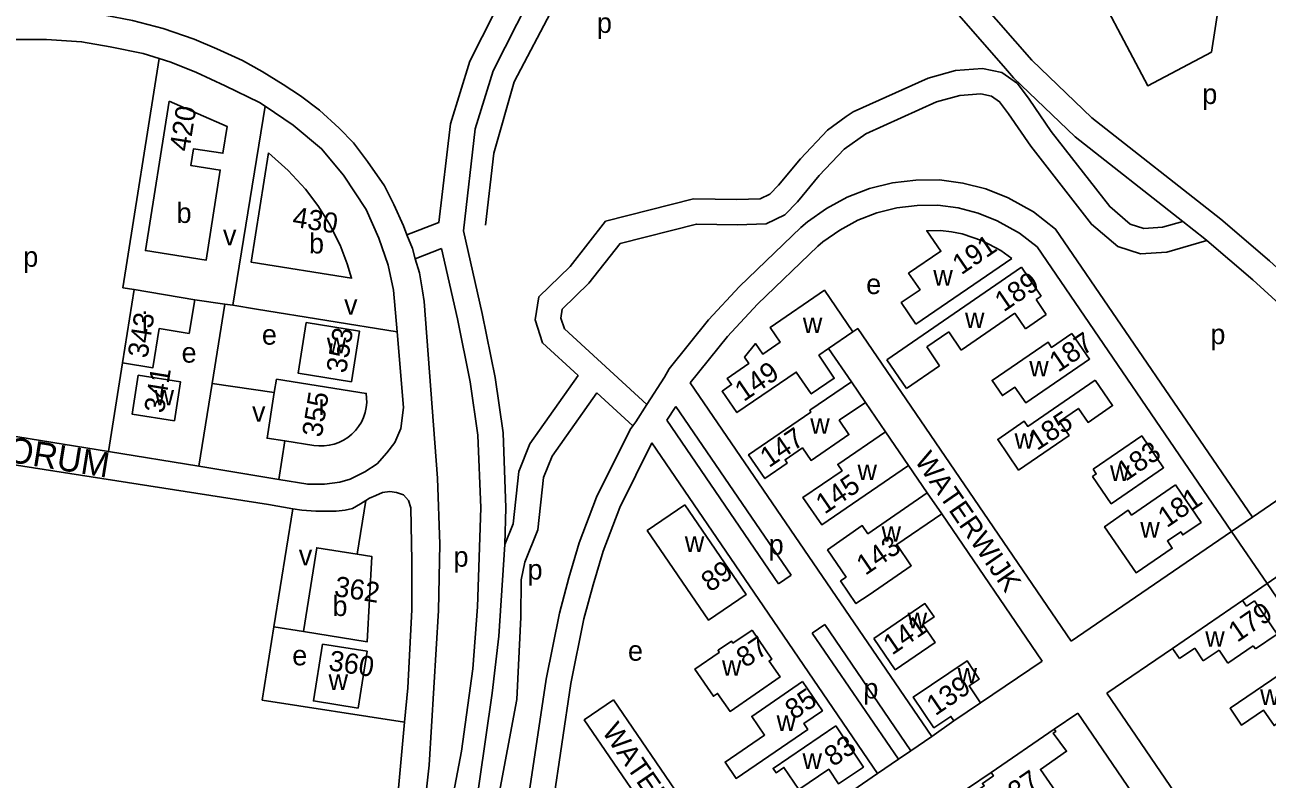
# Model space of a CAD drawing. Extents: x 154320 to 156262, y 382651 to 384180.
# Drawn here: x 155307.4 to 155553.7, y 383322.8 to 383472.2 of the extents above; entities that cross this region are included whole.
import ezdxf

# ---------------------------------------------------------------- set-up
doc = ezdxf.new("R2010")
doc.units = 0
for name, color, linetype in [('BLT_Basislijn', 7, 'Continuous'), ('BLT_Bebouwing', 7, 'Continuous'), ('BLT_Centroide', 7, 'Continuous'), ('BLT_Huisnummer', 7, 'Continuous'), ('BLT_Straatnaam', 7, 'Continuous'), ('BLT_Vlakafsluiter', 7, 'Continuous')]:
    doc.layers.add(name, color=color, linetype=linetype)

msp = doc.modelspace()

# ---------------------------------------------------------------- linework, layer by layer
at = {"layer": 'BLT_Basislijn'}
for p, q in [((155347.08, 383416.87), (155341.13, 383417.73)), ((155347.08, 383416.87), (155344.56, 383401.15)), ((155348.64, 383416.64), (155347.08, 383416.87)), ((155471.24, 383401.47), (155466.74, 383408.06)), ((155326.75, 383405.24), (155323.99, 383387.63)), ((155344.56, 383401.15), (155341.92, 383384.73)), ((155439.3, 383401.25), (155487.17, 383331.21)), ((155436.42, 383396.6), (155459.29, 383363.15)), ((155477.99, 383391.56), (155474.03, 383397.39)), ((155456.81, 383361.45), (155434.66, 383393.86)), ((155358.95, 383389.76), (155357.73, 383382.13)), ((155452.89, 383358.32), (155431.66, 383389.39)), ((155373.27, 383367.31), (155374.97, 383377.96)), ((155546.61, 383371.83), (155514.83, 383350.11)), ((155553.66, 383361.51), (155557.79, 383364.33)), ((155456.81, 383361.45), (155459.29, 383363.15)), ((155548.79, 383358.16), (155553.66, 383361.51)), ((155476.44, 383323.87), (155452.89, 383358.32)), ((155362.62, 383352), (155356.79, 383352.93)), ((155463.49, 383351.67), (155465.97, 383353.37)), ((155480.57, 383326.69), (155463.49, 383351.67)), ((155465.97, 383353.37), (155483.05, 383328.38)), ((155521.89, 383339.79), (155534.9, 383348.67)), ((155509.05, 383346.16), (155496.84, 383337.85)), ((155521.89, 383339.79), (155585.65, 383246.5)), ((155491.56, 383334.34), (155487.17, 383331.21)), ((155511.44, 383332.68), (155516.11, 383335.84)), ((155516.11, 383335.84), (155555.91, 383277.62)), ((155487.17, 383331.21), (155483.05, 383328.38)), ((155483.05, 383328.38), (155480.57, 383326.69)), ((155480.57, 383326.69), (155476.44, 383323.87)), ((155476.44, 383323.87), (155447.55, 383304.12)), ((155494.24, 383320.89), (155498.93, 383324.09))]:
    msp.add_line(p, q, dxfattribs=at)
for points in [[(155698.05, 383531.88), (155690.89, 383537.69), (155681.93, 383540.29), (155671.11, 383539.57), (155664.57, 383538.95), (155596.99, 383507.93), (155581.65, 383515.6), (155558.93, 383498.71), (155544.8, 383480.89), (155542.65, 383466.76)], [(155473.87, 383522.91), (155483.98, 383497.86), (155486.36, 383493.38), (155496.62, 383477.01), (155506.99, 383465.16), (155518.91, 383453.74), (155544.48, 383433.68), (155554.14, 383425.4), (155573.89, 383407.44), (155578.88, 383402.26), (155583.05, 383396.74)], [(155469.2, 383521.12), (155479.44, 383495.74), (155482.03, 383490.88), (155492.59, 383474.01), (155501.8, 383463.51)], [(155465.31, 383513.49), (155448.18, 383506.86), (155432.53, 383497.96), (155422.89, 383489.79), (155412.29, 383475.83), (155404.43, 383460.88), (155400.38, 383446.77), (155398.74, 383432.48)], [(155542.65, 383466.76), (155530.01, 383460.09), (155516.89, 383484.95), (155499.97, 383479.97), (155484.43, 383512.94)], [(155421.03, 383501.28), (155409.88, 383490.01), (155402.96, 383479.51), (155395.61, 383464.95), (155391.76, 383452.59), (155389.49, 383433.02), (155383.15, 383430.57)], [(155424.44, 383497.62), (155413.79, 383486.85), (155407.29, 383476.99), (155400.26, 383463.07), (155396.67, 383451.55), (155394.33, 383431.37)], [(155296.71, 383474.89), (155302.03, 383475.13), (155307.58, 383475.24), (155313.6, 383475.13), (155318.8, 383474.65), (155323.28, 383474.06), (155328.72, 383473), (155334.86, 383471.46), (155341, 383469.34), (155345.49, 383467.45), (155350.56, 383465.08), (155354.46, 383462.96), (155358.59, 383460.36), (155362.02, 383458.11), (155365.8, 383455.28), (155369.69, 383451.73), (155372.53, 383448.78), (155375.36, 383445.12), (155378.67, 383440.28), (155380.56, 383436.61), (155382.45, 383432.36), (155383.15, 383430.57)], [(155304.29, 383469.27), (155311.69, 383469.27), (155318.65, 383468.83), (155324.31, 383467.82), (155330.84, 383466.51), (155334.05, 383465.5)], [(155329.08, 383419.74), (155326.85, 383420.09), (155334.05, 383465.5)], [(155334.05, 383465.5), (155336.36, 383464.77), (155341.43, 383462.74), (155347.09, 383460.12), (155353.91, 383456.78), (155355.02, 383456.04)], [(155501.05, 383462.74), (155497.22, 383463.53), (155491.9, 383463.14), (155486.45, 383461.64), (155471.59, 383454.96), (155470.24, 383454)], [(155536.92, 383433.25), (155532.93, 383432.09), (155529.19, 383431.84), (155526.54, 383432.7), (155522.47, 383436.16), (155510.84, 383451.07), (155506.47, 383457.45), (155504.15, 383460.56), (155501.05, 383462.74)], [(155501.8, 383463.51), (155503.38, 383461.7), (155515.63, 383449.96), (155536.92, 383433.25)], [(155541.74, 383429.44), (155533.8, 383427.14), (155528.56, 383426.79), (155524.06, 383428.25), (155518.84, 383432.68), (155506.8, 383448.12), (155502.4, 383454.54), (155500.62, 383456.93), (155499.02, 383458.05), (155496.88, 383458.5), (155492.75, 383458.19), (155488.15, 383456.92), (155474.09, 383450.6), (155469.81, 383447.56), (155464.88, 383442.33), (155460.54, 383437.08), (155458.05, 383434.51), (155454.34, 383432.77), (155448.58, 383432.55), (155440.53, 383432.69), (155425.41, 383428.83), (155419.22, 383420.97), (155413.95, 383415.85), (155413.67, 383414.1), (155414.35, 383411.97), (155430.71, 383396.96)], [(155355.02, 383456.04), (155348.64, 383416.64)], [(155355.02, 383456.04), (155360.59, 383452.29), (155366.24, 383447.64), (155370.6, 383442.42), (155375.09, 383435.59), (155377.56, 383429.93), (155379.45, 383424.56), (155380.46, 383419.63), (155381.19, 383411.37)], [(155470.24, 383454), (155466.51, 383451.34), (155461.13, 383445.64), (155456.81, 383440.42), (155455.1, 383438.64), (155453.14, 383437.73), (155448.52, 383437.55), (155439.95, 383437.7), (155422.53, 383433.26)], [(155550.74, 383374.65), (155511.74, 383431.71), (155507.33, 383435.11), (155502.31, 383437.9), (155497.93, 383439.67), (155493.37, 383440.82), (155488.7, 383441.44), (155484, 383441.4), (155479.37, 383440.85), (155474.82, 383439.73), (155470.4, 383438.04), (155466.3, 383435.78), (155462.55, 383433.16), (155461.26, 383432.06), (155449.1, 383420.32), (155442.92, 383413.75), (155435.14, 383404.06), (155434.19, 383402.37), (155430.71, 383396.96)], [(155546.61, 383371.83), (155508.06, 383428.23), (155504.57, 383430.92), (155500.15, 383433.38), (155496.37, 383434.9), (155492.43, 383435.9), (155488.39, 383436.43), (155484.32, 383436.41), (155480.27, 383435.92), (155476.32, 383434.95), (155472.51, 383433.5), (155468.95, 383431.53), (155465.61, 383429.2), (155464.62, 383428.36), (155452.66, 383416.81), (155446.69, 383410.46), (155439.3, 383401.25)], [(155422.53, 383433.26), (155415.5, 383424.32), (155409.27, 383418.28), (155408.54, 383413.71), (155410, 383409.18), (155417.06, 383402.7)], [(155536.92, 383433.25), (155541.31, 383429.81), (155541.74, 383429.44)], [(155383.15, 383430.57), (155384.22, 383427.87), (155384.81, 383425.85)], [(155394.33, 383431.37), (155398.09, 383414.99), (155400.64, 383402.31), (155402.2, 383391.37), (155402.77, 383376.53), (155402.53, 383369.27)], [(155390.01, 383427.86), (155384.81, 383425.85)], [(155390.01, 383427.86), (155393.2, 383413.94), (155395.71, 383401.46), (155397.21, 383390.92), (155397.77, 383376.52), (155397.11, 383356.92)], [(155541.74, 383429.44), (155550.83, 383421.65), (155570.4, 383403.86), (155575.07, 383399.01), (155578.92, 383393.92)], [(155384.81, 383425.85), (155385.64, 383423.03), (155386.23, 383419.48)], [(155386.23, 383419.48), (155386.58, 383417.36), (155389.18, 383382.39), (155389.65, 383369.28), (155389.42, 383356.16), (155387.53, 383325.56), (155384.81, 383300.64), (155382.33, 383285.63), (155376.66, 383260.47), (155375.61, 383256.54)], [(155348.64, 383416.64), (155353.32, 383415.88)], [(155353.32, 383415.88), (155381.19, 383411.37)], [(155381.19, 383411.37), (155382.49, 383396.4), (155381.91, 383392.19), (155380.75, 383389.44), (155379.16, 383387.4), (155377.27, 383385.23), (155374.8, 383383.63), (155371.9, 383382.18), (155369.87, 383381.6), (155366.82, 383381.16), (155363.49, 383381.16), (155357.73, 383382.13)], [(155471.56, 383411.38), (155472.52, 383412.02), (155514.83, 383350.11)], [(155323.99, 383387.63), (155241.03, 383401.05)], [(155356.86, 383399.33), (155344.56, 383401.15)], [(155417.06, 383402.7), (155407.5, 383389.15), (155405.35, 383383.72), (155404.19, 383373.36), (155402.53, 383369.27)], [(155420.78, 383399.29), (155411.93, 383386.75), (155410.24, 383382.5), (155409.08, 383372.12), (155406.49, 383365.71), (155405.77, 383362.27), (155405.72, 383354.87), (155404.9, 383338.55), (155401.26, 383318.86), (155401.08, 383304.41), (155399.6, 383288.97), (155400.55, 383285.26), (155403.6, 383277.76)], [(155420.78, 383399.29), (155427.92, 383392.74)], [(155430.71, 383396.96), (155428.49, 383393.51), (155427.92, 383392.74)], [(155436.42, 383396.6), (155434.66, 383393.86)], [(155360.52, 383376.32), (155355.71, 383377.14), (155245.96, 383394.26)], [(155578.92, 383393.92), (155550.74, 383374.65)], [(155427.92, 383392.74), (155427.38, 383392), (155420.75, 383378.59), (155417.28, 383369.55), (155415.24, 383362.63), (155413.37, 383355.63), (155410.73, 383342.59), (155407.13, 383318.3), (155405.98, 383307.32), (155405.59, 383297.75), (155406.01, 383288.13), (155407.17, 383279.22)], [(155412.12, 383279.91), (155410.99, 383288.56), (155410.59, 383297.76), (155410.96, 383306.96), (155412.09, 383317.67), (155415.66, 383341.72), (155418.24, 383354.49), (155420.06, 383361.28), (155422.02, 383367.95), (155425.33, 383376.59), (155431.66, 383389.39)], [(155341.92, 383384.73), (155323.99, 383387.63)], [(155357.73, 383382.13), (155351.44, 383383.19), (155341.92, 383384.73)], [(155486.3, 383379.45), (155482.58, 383384.89)], [(155382.68, 383334.05), (155383.31, 383340.82), (155384.12, 383356.32), (155384.12, 383366), (155383.95, 383376.5), (155383.47, 383377.95), (155382.5, 383379.08), (155381.05, 383379.57), (155379.76, 383379.73), (155378.3, 383379.57), (155377.01, 383378.92), (155375.72, 383378.44), (155374.97, 383377.96)], [(155360.52, 383376.32), (155356.79, 383352.93)], [(155374.97, 383377.96), (155373.95, 383377.31), (155372.33, 383376.34), (155370.88, 383376.01), (155369.11, 383375.85), (155367.49, 383375.85), (155365.07, 383375.85), (155362.33, 383376.01), (155360.52, 383376.32)], [(155509.05, 383346.16), (155489.16, 383375.33)], [(155550.74, 383374.65), (155546.61, 383371.83)], [(155402.53, 383369.27), (155401.34, 383351.06), (155400.02, 383339.82), (155396.19, 383313.18)], [(155553.66, 383361.51), (155617.43, 383268.23)], [(155397.11, 383356.92), (155396.22, 383344.6), (155393.98, 383328.27), (155391.12, 383313.39)], [(155356.79, 383352.93), (155354.48, 383338.43), (155382.68, 383334.05)], [(155441.77, 383300.17), (155418.3, 383334.5), (155424.08, 383338.45)], [(155424.08, 383338.45), (155447.55, 383304.12)], [(155221.43, 383321.6), (155362.65, 383299.48), (155367.81, 383299.16), (155371.04, 383300.13), (155373.46, 383301.91), (155376.37, 383304.17), (155378.79, 383307.23), (155379.92, 383309.82), (155380.73, 383312.72), (155381.05, 383316.6), (155382.68, 383334.05)]]:
    msp.add_lwpolyline(points, dxfattribs=at)
at = {"layer": 'BLT_Bebouwing'}
for p, q in [((155503.06, 383425.9), (155484.03, 383412.9)), ((155478.26, 383405.83), (155504.99, 383424.16)), ((155504.99, 383424.16), (155508.9, 383418.45)), ((155329.08, 383419.74), (155326.75, 383405.24)), ((155341.13, 383417.73), (155329.08, 383419.74)), ((155508.9, 383418.45), (155507.85, 383417.75)), ((155507.85, 383417.75), (155509.87, 383414.78)), ((155503.62, 383415.08), (155492.99, 383407.76)), ((155505.77, 383411.96), (155503.62, 383415.08)), ((155509.87, 383414.78), (155505.77, 383411.96)), ((155490.55, 383411.35), (155486.2, 383408.36)), ((155492.99, 383407.76), (155490.55, 383411.35)), ((155486.2, 383408.36), (155488.74, 383404.65)), ((155482.16, 383400.14), (155478.26, 383405.83)), ((155488.74, 383404.65), (155482.16, 383400.14)), ((155477.99, 383391.56), (155482.58, 383384.89)), ((155486.3, 383379.45), (155489.16, 383375.33)), ((155534.9, 383348.67), (155548.79, 383358.16)), ((155548.79, 383358.16), (155549.58, 383357)), ((155549.58, 383357), (155551.17, 383358.09)), ((155551.17, 383358.09), (155555.66, 383351.45)), ((155555.66, 383351.45), (155551.36, 383348.55)), ((155550.91, 383349.19), (155545.88, 383345.75)), ((155551.36, 383348.55), (155550.91, 383349.19)), ((155536.31, 383346.63), (155534.9, 383348.67)), ((155539.31, 383348.68), (155536.31, 383346.63)), ((155540.96, 383346.19), (155539.31, 383348.68)), ((155544.14, 383348.31), (155540.96, 383346.19)), ((155545.88, 383345.75), (155544.14, 383348.31)), ((155496.84, 383337.85), (155491.56, 383334.34)), ((155498.93, 383324.09), (155511.44, 383332.68))]:
    msp.add_line(p, q, dxfattribs=at)
for points in [[(155336.03, 383457.05), (155347.5, 383452.05), (155346.67, 383446.72), (155340.84, 383447.6), (155340.34, 383444.28), (155346.15, 383443.4), (155343.32, 383425.54), (155331.32, 383427.44)], [(155355.71, 383446.8), (155359.62, 383443.34), (155363.04, 383439.64), (155365.48, 383436.36), (155367.71, 383432.82), (155369.88, 383428.51), (155371.29, 383424.8), (155372.19, 383421.96), (155352.29, 383425.15)], [(155363.17, 383413.18), (155373.73, 383411.52), (155372.15, 383401.49), (155361.59, 383403.15)], [(155514.95, 383411.05), (155518.46, 383405.95), (155505.82, 383397.32), (155503.68, 383400.39), (155501.2, 383398.72), (155499.15, 383401.75), (155510.27, 383409.29), (155510.91, 383408.27)], [(155329.9, 383402.77), (155338.26, 383401.47), (155337.05, 383393.74), (155328.69, 383395.05)], [(155519.56, 383401.82), (155523.04, 383396.76), (155518.17, 383393.42), (155516.25, 383396.2), (155512.49, 383393.62), (155514.4, 383390.83), (155504.4, 383383.98), (155500.25, 383390.04), (155505.52, 383393.64), (155506.2, 383392.64)], [(155519.17, 383384.13), (155528.82, 383390.75), (155533.15, 383384.43), (155522.76, 383377.3), (155519.05, 383382.7), (155519.8, 383383.21)], [(155535.47, 383381.06), (155540.56, 383373.61), (155536.95, 383371.15), (155536.53, 383371.75), (155533.88, 383369.94), (155534.85, 383368.5), (155527.69, 383363.64), (155521.43, 383372.77), (155526.14, 383376.01), (155526.78, 383375.08)], [(155438.24, 383377.11), (155450.39, 383359.33), (155442.93, 383354.23), (155430.77, 383372)], [(155475.69, 383350.63), (155485.82, 383357.55), (155487.63, 383354.89), (155485.42, 383353.38), (155487.85, 383349.82), (155479.93, 383344.42)], [(155451.57, 383352.3), (155455.5, 383346.55), (155454.93, 383346.16), (155457.1, 383343.01), (155447.2, 383336.17), (155444.74, 383339.74), (155443.9, 383339.19), (155440.24, 383344.55), (155445.06, 383347.85), (155444.81, 383348.28), (155447.46, 383350.1), (155447.75, 383349.7)], [(155366.4, 383349.49), (155375.26, 383348.08), (155373.48, 383336.83), (155364.6, 383338.25)], [(155559.55, 383345.79), (155563.92, 383339.45), (155555.04, 383333.38), (155552.97, 383336.41), (155548.57, 383333.47), (155546.31, 383336.79)], [(155461.56, 383342.08), (155465.51, 383336.3), (155461.8, 383333.76), (155462.59, 383332.61), (155448.4, 383322.9), (155446.22, 383326.13), (155454.05, 383331.48), (155451.5, 383335.2)]]:
    msp.add_lwpolyline(points, close=True, dxfattribs=at)
for points in [[(155503.06, 383425.9), (155500.86, 383427.5), (155497.24, 383429.4), (155493.19, 383430.77), (155491.09, 383431.2), (155488.91, 383431.41), (155486.2, 383431.4), (155488.98, 383427.32), (155482.6, 383422.98), (155484.87, 383419.71), (155481.13, 383417.16), (155484.03, 383412.9)], [(155466.74, 383408.06), (155464.81, 383406.74), (155467.85, 383402.18), (155463.28, 383399.07), (155460.33, 383403.4), (155448.56, 383395.36), (155445.63, 383399.61), (155447.49, 383400.9), (155446.64, 383402.12), (155450.94, 383405.1), (155450.09, 383406.33), (155452.25, 383409.04), (155453.68, 383406.94), (155457.15, 383409.32), (155455.15, 383412.25), (155465.9, 383419.61), (155471.56, 383411.38)], [(155326.75, 383405.24), (155332.78, 383404.24), (155334.04, 383412.02), (155339.98, 383411.06), (155341.13, 383417.73)], [(155471.56, 383411.38), (155466.74, 383408.06)], [(155356.86, 383399.33), (155357.29, 383402)], [(155357.29, 383402), (155375.09, 383399.18), (155375.17, 383397.39), (155375.06, 383396.37), (155374.85, 383395.38), (155374.54, 383394.41), (155374.11, 383393.5), (155373.58, 383392.64), (155372.95, 383391.83), (155372.24, 383391.11), (155371.44, 383390.46), (155370.6, 383389.92), (155369.67, 383389.46), (155368.72, 383389.13), (155367.74, 383388.9), (155366.71, 383388.78), (155365.71, 383388.77), (155364.71, 383388.87), (155358.95, 383389.76)], [(155474.03, 383397.39), (155468.84, 383393.84), (155470.77, 383391.01), (155463.25, 383385.88), (155461.55, 383388.37), (155458.1, 383386.01), (155458.55, 383385.35), (155454.1, 383382.31), (155450.88, 383387.01), (155463.24, 383395.47), (155463, 383395.82), (155471.24, 383401.47)], [(155471.24, 383401.47), (155474.03, 383397.39)], [(155358.95, 383389.76), (155355.43, 383390.3), (155356.86, 383399.33)], [(155482.58, 383384.89), (155465.39, 383373.15), (155461.64, 383378.57), (155469.39, 383383.84), (155468.54, 383385.09), (155477.99, 383391.56)], [(155489.16, 383375.33), (155480.24, 383369.25), (155483.11, 383365.02), (155474.77, 383359.3), (155472.15, 383357.54), (155469.1, 383362.02), (155470.21, 383362.77), (155466.52, 383368.18), (155473.41, 383372.99), (155474.54, 383371.36), (155486.3, 383379.45)], [(155362.62, 383352), (155365.28, 383368.59), (155373.27, 383367.31)], [(155373.27, 383367.31), (155376.2, 383366.84), (155375.29, 383349.97), (155362.62, 383352)], [(155491.56, 383334.34), (155490.99, 383335.2), (155487.6, 383332.93), (155483.52, 383339), (155494.2, 383346.17), (155496.6, 383342.57), (155494.58, 383341.22), (155496.84, 383337.85)], [(155468.15, 383333.34), (155473.62, 383325.15), (155468.72, 383321.82), (155466.76, 383324.72), (155460.85, 383320.69), (155457.88, 383325.09), (155456.31, 383324.03), (155455.74, 383324.88), (155468.15, 383333.34)], [(155511.44, 383332.68), (155511.76, 383332.22), (155511.28, 383331.89), (155513.9, 383328.28), (155508.71, 383324.68), (155511.7, 383320.41), (155509.79, 383319.11), (155510.34, 383318.33), (155501.73, 383312.47), (155496.17, 383320.48), (155497.58, 383321.43), (155497.23, 383321.93), (155498.53, 383322.83), (155499.39, 383323.42), (155498.93, 383324.09)]]:
    msp.add_lwpolyline(points, dxfattribs=at)
at = {"layer": 'BLT_Vlakafsluiter'}
msp.add_line((155546.61, 383371.83), (155553.66, 383361.51), dxfattribs=at)

# ---------------------------------------------------------------- texts
at = {"layer": 'BLT_Centroide'}
for s, p in [('p', (155420.81, 383470.57)), ('p', (155540.81, 383456.49)), ('b', (155337.48, 383432.93)), ('v', (155346.68, 383428.51)), ('b', (155363.74, 383426.89)), ('p', (155307.1, 383424.25)), ('w', (155487.49, 383420.51)), ('i', (155330.58, 383411.2)), ('v', (155370.69, 383414.76)), ('w', (155461.63, 383411.11)), ('w', (155493.77, 383412.11)), ('e', (155354.4, 383408.82)), ('p', (155542.42, 383408.91)), ('e', (155338.48, 383405.26)), ('w', (155367.28, 383407.12)), ('w', (155506.51, 383402.54)), ('w', (155333.12, 383396.78)), ('i', (155365.61, 383394.91)), ('v', (155352.44, 383393.54)), ('w', (155463.1, 383391.16)), ('w', (155503.59, 383388.21)), ('w', (155472.46, 383381.99)), ('w', (155522.53, 383381.82)), ('w', (155528.52, 383370.6)), ('w', (155477.23, 383369.78)), ('w', (155438.23, 383367.77)), ('v', (155361.71, 383365.12)), ('p', (155392.39, 383364.84)), ('p', (155407.06, 383362.29)), ('b', (155368.39, 383355.07)), ('w', (155482.4, 383352.66)), ('w', (155541.39, 383348.98)), ('e', (155360.42, 383345.3)), ('w', (155445.6, 383343.24)), ('w', (155492.3, 383341.72)), ('w', (155367.61, 383340.42)), ('w', (155552.27, 383337.45)), ('w', (155456.43, 383332.3)), ('w', (155461.56, 383324.79))]:
    msp.add_text(s, height=4, dxfattribs=at).set_placement(p)
for s, p in [('e', (155474.17, 383418.86)), ('p', (155454.84, 383367.23)), ('e', (155426.95, 383346.23)), ('p', (155473.61, 383338.74))]:
    msp.add_text(s, height=4, rotation=359.5, dxfattribs=at).set_placement(p)
at = {"layer": 'BLT_Huisnummer'}
for s, rotation, p in [('420', 80.7958, (155339.99, 383446.95)), ('430', 350.7958, (155360.28, 383432.23)), ('191', 34.3541, (155493.03, 383422.54)), ('189', 34.3541, (155501.44, 383415.19)), ('343', 80.7958, (155331.7, 383406.01)), ('353', 80.7958, (155371.07, 383403.04)), ('187', 34.3542, (155512.24, 383403.22)), ('341', 80.7958, (155334.96, 383395.11)), ('149', 34.353, (155449.9, 383397.42)), ('355', 80.7958, (155366.25, 383390.34)), ('185', 33.2749, (155508.05, 383387.73)), ('147', 34.3538, (155454.91, 383384.34)), ('183', 34.3542, (155525.6, 383381.63)), ('145', 34.3538, (155465.95, 383375.13)), ('181', 34.3542, (155533.77, 383372.44)), ('143', 34.3538, (155474.01, 383363)), ('89', 34.3536, (155443.23, 383359.68)), ('362', 350.9037, (155368.58, 383359.07)), ('179', 34.3539, (155547.73, 383349.74)), ('141', 34.3538, (155479.31, 383347.21)), ('87', 34.3536, (155450.21, 383344.69)), ('360', 350.9355, (155367.46, 383344.38)), ('139', 34.3538, (155487.89, 383335.2)), ('85', 34.3536, (155459.86, 383334.39)), ('83', 34.3536, (155467.62, 383325.1)), ('137', 34.3538, (155501.58, 383316.46))]:
    msp.add_text(s, height=4, rotation=rotation, dxfattribs=at).set_placement(p)
at = {"layer": 'BLT_Straatnaam'}
for s, height, rotation, p in [('PARK FORUM', 5, 350.8268, (155279.75, 383389.55)), ('WATERWIJK', 4, 304.5737, (155483.66, 383385.88)), ('WATERWIJK', 4, 304.5737, (155421.69, 383332.19))]:
    msp.add_text(s, height=height, rotation=rotation, dxfattribs=at).set_placement(p)

doc.saveas('drawing.dxf')
